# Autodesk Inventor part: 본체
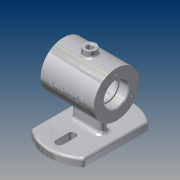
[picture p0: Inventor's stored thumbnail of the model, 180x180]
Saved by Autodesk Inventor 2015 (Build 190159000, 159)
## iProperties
Created: 2017-12
Part Number: 본체
Material: 알루미늄 6061
Document SubType Name: Modeling
Designer: 2-PC06
Mass: 468.258 g
Surface Area: 488.266 cm^2
Volume: 173.429 cm^3
Density: 2.7 g/cm^3
Appearance: 알루미늄 - 평지
Author: 2-PC06
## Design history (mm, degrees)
sketch "스케치1"
  geometry: L1 (-35, 42.426)-(-35, -42.426); L2 (35, 42.426)-(35, -42.426); L3 (0, 40)-(0, 24); L4 (5, 40)-(5, 24); L5 (-5, 24)-(-5, 40); L6 (0, -24)-(0, -40); L7 (5, -24)-(5, -40); L8 (-5, -40)-(-5, -24); A1 r 55 centre (0, 0) between (-35, -42.426) and (35, -42.426); A2 r 55 centre (0, 0) between (35, 42.426) and (-35, 42.426); A3 r 5 centre (0, 40) between (5, 40) and (-5, 40); A4 r 5 centre (0, 24) between (-5, 24) and (5, 24); A5 r 5 centre (0, -24) between (5, -24) and (-5, -24); A6 r 5 centre (0, -40) between (-5, -40) and (5, -40); 3 further points
  constraints: 20 end point, 12 point on circle, 8 tangent, 6 centre point, 3 vertical, 2 midpoint, 2 parallel, 2 point on line, 1 coincident, 1 concentric, 1 vertical alignment
  dimensions: "d1" = 70 distance between parallel lines of L2 L1; "d2" = 35 distance from line of point (0, 0) L1; "d4" = 110 diameter of A2; "d5" = 5 radius of A3; "d6" = 5 radius of A5; "d7" = 16 distance of L3.start L3.end; "d8" = 16 distance of L6.start L6.end; "d9" = 24 distance of point (0, 0) L3.end; "d10" = 24 distance of L6.start point (0, 0)
extrude "돌출1" new body sketch "스케치1" distance "d11" = 10; taper "d12" = 0 deg
sketch "스케치9"
  geometry: L1 (19, 10)-(19, 0) reference; L2 (19, 0)-(-19, 0) reference; L3 (-19, 0)-(-19, 10) reference; L4 (-19, 10)-(19, 10) reference; L5 (55, 10)-(55, 0) reference; L6 (55, 0)-(45, 0) reference; L7 (45, 0)-(45, 10) reference; L8 (45, 10)-(55, 10) reference; L9 (-55, 0)-(-55, 10) reference; L10 (-55, 10)-(-45, 10) reference; L11 (-45, 10)-(-45, 0) reference; L12 (-45, 0)-(-55, 0) reference; C1 r 30 at (0, 62); 2 further points
  constraints: 1 centre point, 1 midpoint, 1 vertical alignment
  dimensions: "d66" = 60 diameter of C1; "d67" = 62 distance from line of L12 C1.centre
extrude "돌출5" join sketch "스케치9" stored distance "d68" = 70; taper "d69" = 0 deg
sketch "스케치10"
  geometry: L1 (-15, 0)-(15, 0); L2 (-15, 5)-(15, 5); L3 (15, -5)-(-15, -5); A1 r 5 centre (-15, 0) between (-15, 5) and (-15, -5); A2 r 5 centre (15, 0) between (15, -5) and (15, 5); 1 further point
  constraints: 8 end point, 4 point on circle, 4 tangent, 2 centre point, 1 horizontal, 1 midpoint, 1 parallel
  dimensions: "d70" = 5 radius of A2; "d71" = 30 distance of L1.start L1.end
extrude "돌출6" join sketch "스케치10" stored distance "d72" = 70; taper "d73" = 0 deg
sketch "스케치11"
  geometry: L1 (35, 10)-(35, 0) reference; L2 (35, 0)-(-35, 0) reference; L3 (-35, 0)-(-35, 10) reference; L4 (-35, 10)-(-20, 10) reference; L5 (-20, 10)-(-20, 32) reference; L6 (-20, 32)-(-35, 32) reference; L7 (-35, 32)-(-35, 92) reference; L8 (-35, 92)-(35, 92) reference; L9 (35, 92)-(35, 32) reference; L10 (35, 32)-(20, 32) reference; L11 (20, 32)-(20, 10) reference; L12 (20, 10)-(35, 10) reference; L13 (35, 62)-(-35, 62); L14 (35, 62)-(35, 78); L15 (35, 32)-(35, 92) reference; L16 (35, 78)-(23.3, 78); L17 (23, 77.7)-(23, 76); L18 (23, 76)-(20, 76); L19 (20, 76)-(20, 84); L20 (17, 87)-(-17, 87); L21 (-20, 84)-(-20, 76); L22 (-20, 76)-(-23, 76); L23 (-23, 76)-(-23, 77.7); L24 (-23.3, 78)-(-35, 78); L25 (-35, 62)-(-35, 78); L26 (-35, 92)-(-35, 32) reference; A1 r 3 centre (17, 84) between (20, 84) and (17, 87); A2 r 3 centre (-17, 84) between (-17, 87) and (-20, 84); A3 r 0.3 centre (23.3, 77.7) between (23.3, 78) and (23, 77.7); A4 r 0.3 centre (-23.3, 77.7) between (-23, 77.7) and (-23.3, 78); 5 further points
  constraints: 24 end point, 14 point on line, 8 point on circle, 8 tangent, 6 perpendicular, 4 centre point, 2 equal radius, 2 midpoint, 1 collinear, 1 horizontal
  dimensions: "d74" = 32 diameter of L24 L13; "d75" = 28 diameter of L18 L13; "d76" = 50 diameter of L20 L13; "d77" = 12 distance of L14.end point (23, 78); "d78" = 12 distance of point (-23, 78) L24.end; "d79" = 3 distance of L17.end L18.end; "d80" = 3 distance of L21.end L22.end; "d81" = 40 distance of point (20, 87) point (-20, 87) (derived); "d82" = 3 radius of A1; "d83" = 0.3 radius of A3
revolve "회전2" sketch "스케치11" stored, may be unused: angle "d84" = 90 deg
node "작업 평면3"
sketch "스케치12"
  geometry: C1 r 8 at (0, 0); 1 further point
  constraints: 1 centre point, 1 coincident
  dimensions: "d86" = 16 diameter of C1
extrude "돌출7" join sketch "스케치12" stored distance "d87" = 70; taper "d88" = 0 deg
sketch "스케치13"
  geometry: 2 further points
  constraints: 1 coincident
hole "구멍3" sketch "스케치13" at (0, 0) diameter "d89" = 8; stored, may be unused: countersink angle "d93" = 90 deg, drill point angle "d95" = 118 deg; dims "d90" = 8, "d91" = 4, "d92" = 2, "d94" = 33
sketch "스케치14" dims "d96" = 46
  geometry: L1 (-62, -42.426)-(-62, 42.426) reference; L2 (-62, 42.426)-(-52, 42.426) reference; L3 (-52, 42.426)-(-52, -42.426) reference; L4 (-52, -42.426)-(-62, -42.426) reference; C1 r 16 at (0, 0) reference; C2 r 30 at (0, 0) reference; 3 further points
  constraints: 2 horizontal alignment, 1 coincident, 2 other
hole "구멍4" sketch "스케치14" at (23, 0) diameter "d97" = 3.242; stored, may be unused: countersink angle "d101" = 90 deg, drill point angle "d103" = 118 deg; dims "d98" = 8, "d99" = 4, "d100" = 2, "d102" = 10
chamfer "모따기2" distance "d107" = 1; stored, may be unused: second distance "d108" = 2, angle "d109" = 45 deg
fillet "모깎기4" dims "d110" = 5, "d111" = 3
fillet "모깎기5" dims "d112" = 3
node "작업 평면4"
sketch "스케치15"
  geometry: L1 (-35, 92)-(-35, 32) reference; 2 further points
  constraints: 1 other
  dimensions: "d114" = 35 distance from line of point (0, 62) L1; "d115" = 30 vertical distance of point (0, 62) L1.start
feature "엠보싱2" sketch "스케치15" dims "d1" = 70, "d2" = 35, "d4" = 110, "d116" = 0.5, "d117" = 0
node "솔리드1"
pattern_circular "원형 패턴2" dims angle "d105" = 360 deg
mirror "대칭2"
node "절단 모서리 투영4"
node "절단 모서리 투영5"
node "절단 모서리 투영6"
other parameters: "d85" = -99, "d113" = 85
